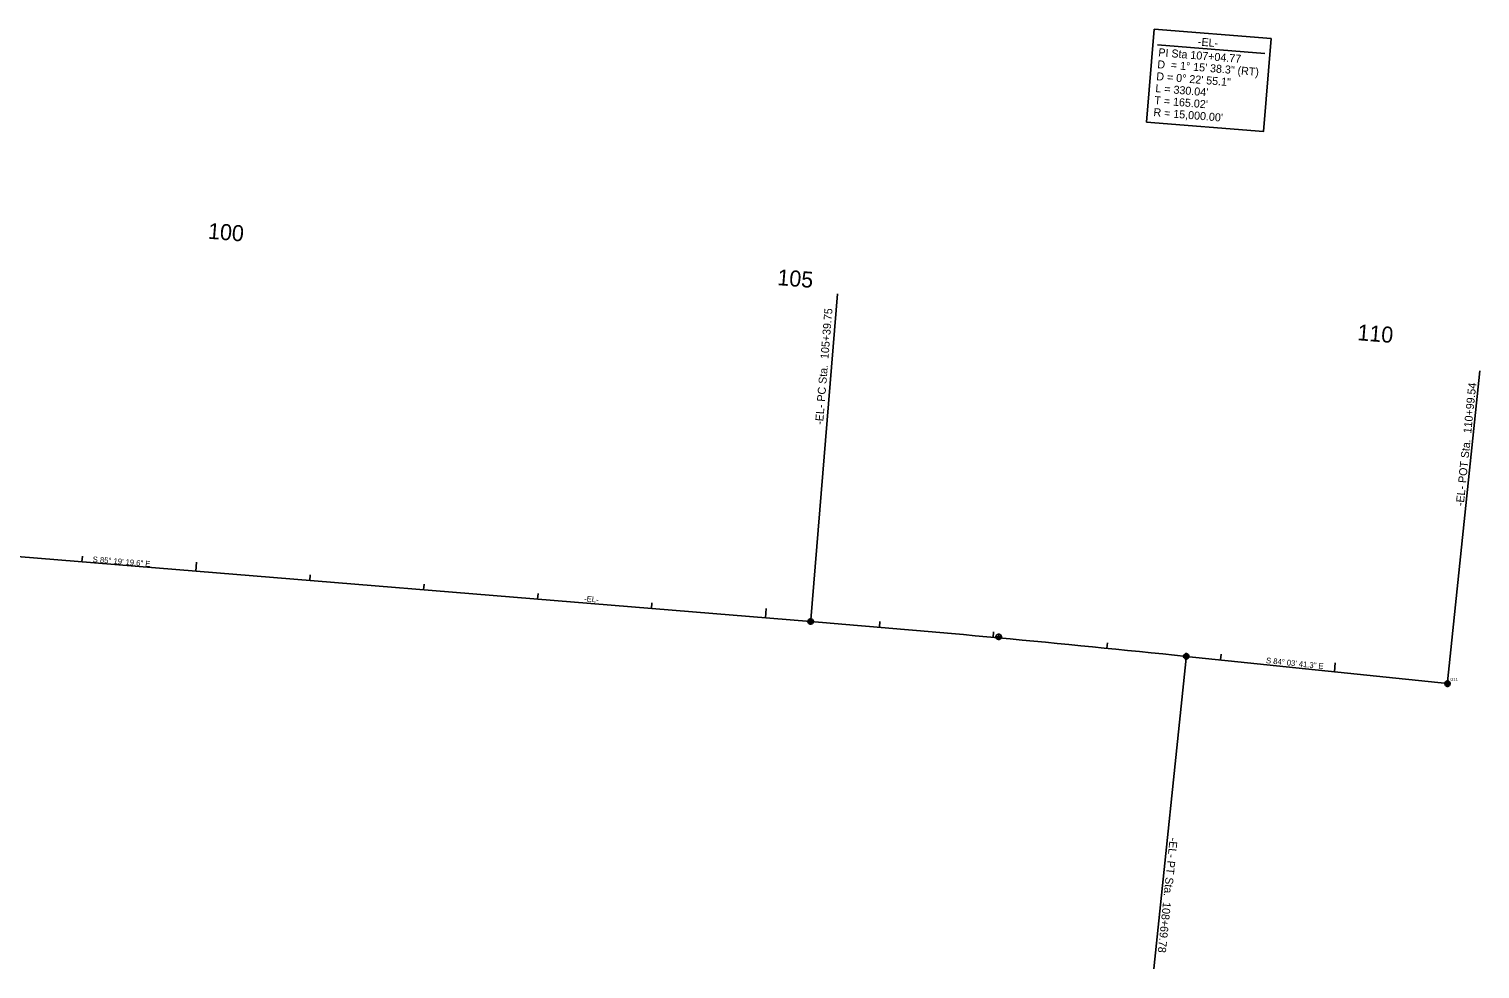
# Model space of a CAD drawing. Extents: x 928071 to 937324, y 684061 to 686812.
# Drawn here: x 936055 to 937324, y 684061 to 684883 of the extents above; entities that cross this region are included whole.
import ezdxf

# ---------------------------------------------------------------- set-up
doc = ezdxf.new("R2010")
doc.units = 0
for name, color, linetype in [('COGO Default Chain', 7, 'Continuous'), ('COGO Default Curve', 7, 'Continuous'), ('Cogo Default Point CELL', 7, 'Continuous'), ('COGO Default Point Number', 7, 'Continuous'), ('Default', 7, 'Continuous'), ('Exist Horizontal Alignment', 7, 'Continuous'), ('Exist Horizontal Alignment Curve and Spiral Data', 7, 'Continuous'), ('Exist Horizontal Alignment Direction Label', 7, 'Continuous'), ('Exist Horizontal Alignment Station Label', 7, 'Continuous'), ('Exist Horizontal Alignment Tick Label', 7, 'Continuous'), ('Exist Horizontal Alignment Tick Large', 7, 'Continuous'), ('Exist Horizontal Alignment Tick Small', 7, 'Continuous'), ('Prop DSN Text', 7, 'Continuous')]:
    doc.layers.add(name, color=color, linetype=linetype)

msp = doc.modelspace()

# ---------------------------------------------------------------- linework, layer by layer
at = {"layer": 'COGO Default Chain'}
for p, q in [((935531.7, 684463.7), (936738.6, 684364.9)), ((937067.2, 684334.4), (937295.8, 684310.6))]:
    msp.add_line(p, q, dxfattribs=at)
msp.add_arc((935515.3, 669414.9), 15000, 84.06147, 85.32211, dxfattribs=at)
at = {"layer": 'COGO Default Curve'}
msp.add_arc((935515.3, 669414.9), 15000, 84.06147, 85.32211, dxfattribs=at)
at = {"layer": 'Cogo Default Point CELL'}
for points in [[(936738.6, 684367.9), (936738.6, 684364.9)], [(936735.6, 684364.9), (936738.6, 684364.9)], [(936738.6, 684364.9), (936741.6, 684364.9)], [(936738.6, 684364.9), (936738.6, 684361.9)], [(936900.1, 684351.5), (936903.1, 684351.5)], [(936903.1, 684354.5), (936903.1, 684351.5)], [(936903.1, 684351.5), (936906.1, 684351.5)], [(936903.1, 684351.5), (936903.1, 684348.5)], [(937064.2, 684334.4), (937067.2, 684334.4)], [(937067.2, 684337.4), (937067.2, 684334.4)], [(937067.2, 684334.4), (937070.2, 684334.4)], [(937067.2, 684334.4), (937067.2, 684331.4)], [(937292.8, 684310.6), (937295.8, 684310.6)], [(937295.8, 684313.6), (937295.8, 684310.6)], [(937295.8, 684310.6), (937298.8, 684310.6)], [(937295.8, 684310.6), (937295.8, 684307.6)]]:
    msp.add_lwpolyline(points, dxfattribs=at)
for centre in [(936738.6, 684364.9), (936903.1, 684351.5), (937067.2, 684334.4), (937295.8, 684310.6)]:
    msp.add_circle(centre, 2.34, dxfattribs=at)
at = {"layer": 'Default'}
for p, q in [((936738.6, 684364.9), (935531.7, 684463.7)), ((937295.8, 684310.6), (937067.2, 684334.4))]:
    msp.add_line(p, q, dxfattribs=at)
msp.add_lwpolyline([(937039.1, 684883.3), (937141.4, 684875), (937134.7, 684793.6), (937032.5, 684801.9)], close=True, dxfattribs=at)
msp.add_arc((935515.3, 669414.9), 15000, 84.06147, 85.32211, dxfattribs=at)
at = {"layer": 'Exist Horizontal Alignment'}
for p, q in [((935531.7, 684463.7), (936738.6, 684364.9)), ((937067.2, 684334.4), (937295.8, 684310.6))]:
    msp.add_line(p, q, dxfattribs=at)
msp.add_arc((935515.3, 669414.9), 15000, 84.06147, 85.32211, dxfattribs=at)
at = {"layer": 'Exist Horizontal Alignment Curve and Spiral Data'}
for p, q in [((937042.2, 684869.4), (937136, 684861.8)), ((937042.6, 684859.6), (937042.6, 684859.6))]:
    msp.add_line(p, q, dxfattribs=at)
at = {"layer": 'Exist Horizontal Alignment Station Label'}
for p, q in [((936762.1, 684651.7), (936738.7, 684366.4)), ((937295.9, 684312.1), (937324.2, 684584.2)), ((937067.1, 684332.9), (937038.8, 684060.9))]:
    msp.add_line(p, q, dxfattribs=at)
for centre in [(936738.6, 684364.9), (937067.2, 684334.4), (937295.8, 684310.6)]:
    msp.add_circle(centre, 1.5, dxfattribs=at)
at = {"layer": 'Exist Horizontal Alignment Tick Large'}
for p, q in [((936200.7, 684409), (936201.3, 684416.9)), ((936699, 684368.2), (936699.7, 684376.2)), ((937196.8, 684320.9), (937197.6, 684328.9))]:
    msp.add_line(p, q, dxfattribs=at)
at = {"layer": 'Exist Horizontal Alignment Tick Small'}
for p, q in [((936101, 684417.1), (936101.4, 684422.1)), ((936300.3, 684400.8), (936300.7, 684405.8)), ((936400, 684392.6), (936400.4, 684397.6)), ((936499.7, 684384.5), (936500.1, 684389.5)), ((936599.3, 684376.3), (936599.7, 684381.3)), ((936798.7, 684359.9), (936799.1, 684364.9)), ((936898.3, 684351), (936898.7, 684356)), ((936997.8, 684341.5), (936998.3, 684346.4)), ((937097.3, 684331.3), (937097.8, 684336.3))]:
    msp.add_line(p, q, dxfattribs=at)

# ---------------------------------------------------------------- texts
at = {"layer": 'COGO Default Point Number'}
msp.add_text('G11', height=2.5, dxfattribs=at).set_placement((937298.3, 684313.1))
at = {"layer": 'Exist Horizontal Alignment Curve and Spiral Data'}
for s, p in [('-EL-', (937077.2, 684868.9)), ('PI Sta 107+04.77', (937042.6, 684859.6)), ('D', (937041.7, 684849.1)), ('= 1%%d 15\' 38.3" (RT)', (937053.5, 684848.5)), ('D = 0%%d 22\' 55.1"', (937040.8, 684838.6)), ("T = 165.02'", (937039.1, 684817.7)), ("L = 330.04'", (937040, 684828.2)), ("R = 15,000.00'", (937038.3, 684807.2))]:
    msp.add_text(s, height=7, rotation=355.3221, dxfattribs=at).set_placement(p)
at = {"layer": 'Exist Horizontal Alignment Direction Label'}
for s, rotation, p in [('S 85%%d 19\' 19.6" E', 355.3221, (936110.3, 684416.9)), ('S 84%%d 03\' 41.3" E', 354.0615, (937136.8, 684328.5))]:
    msp.add_text(s, height=5, rotation=rotation, dxfattribs=at).set_placement(p)
at = {"layer": 'Exist Horizontal Alignment Station Label'}
for s, rotation, p in [('-EL- PC Sta.  105+39.75', 85.3221, (936749.4, 684536.8)), ('-EL- POT Sta.  110+99.54', 84.0615, (937309.9, 684465.6)), ('-EL- PT Sta.  108+69.78', 264.0615, (937052.8, 684176.1))]:
    msp.add_text(s, height=7, rotation=rotation, dxfattribs=at).set_placement(p)
at = {"layer": 'Exist Horizontal Alignment Tick Label'}
for s, rotation, p in [('100', 355.3222, (936211, 684699.9)), ('105', 355.3221, (936709.1, 684659.3)), ('110', 355.3222, (937216.6, 684611.1))]:
    msp.add_text(s, height=14, rotation=rotation, dxfattribs=at).set_placement(p)
at = {"layer": 'Prop DSN Text'}
msp.add_text('-EL-', height=5, rotation=355.6238, dxfattribs=at).set_placement((936540.3, 684382.5))

doc.saveas('drawing.dxf')
